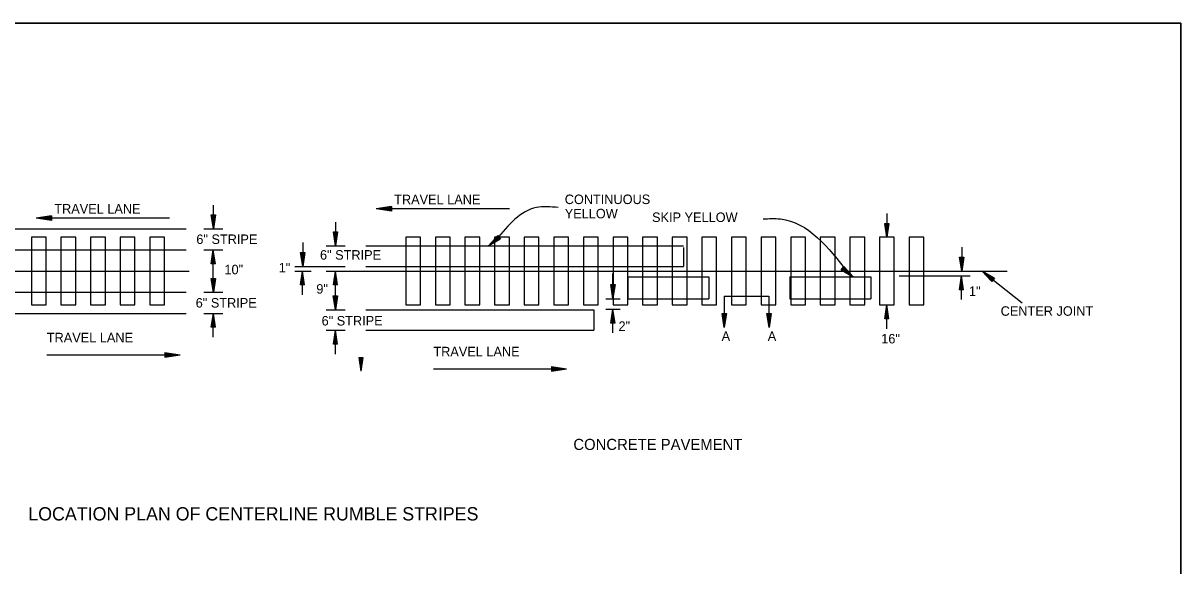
# Model space of a CAD drawing. Extents: x 8229 to 8749, y 14916 to 18021.
# Drawn here: x 8423.6 to 8749, y 16313.4 to 16466 of the extents above; entities that cross this region are included whole.
import ezdxf

# ---------------------------------------------------------------- set-up
doc = ezdxf.new("R2010")
doc.units = 0
doc.layers.add('Default', color=7, linetype='Continuous')
doc.layers.add('R_Draft', color=7, linetype='Continuous')

msp = doc.modelspace()

# ---------------------------------------------------------------- linework, layer by layer
at = {"layer": 'Default'}
for p, q in [((8477.01, 16414.9), (8477.01, 16412.12)), ((8431.51, 16411.84), (8427.26, 16411.2)), ((8431.51, 16411.74), (8427.97, 16411.2)), ((8431.51, 16411.63), (8428.7, 16411.2)), ((8431.51, 16411.52), (8429.41, 16411.2)), ((8431.51, 16411.41), (8430.13, 16411.2)), ((8431.51, 16411.84), (8431.51, 16410.57)), ((8476.45, 16412.12), (8477.03, 16408.21)), ((8476.45, 16412.12), (8477.62, 16412.12)), ((8476.54, 16412.12), (8477.03, 16408.86)), ((8476.64, 16412.12), (8477.03, 16409.53)), ((8476.74, 16412.12), (8477.03, 16410.19)), ((8476.84, 16412.12), (8477.03, 16410.85)), ((8476.94, 16412.12), (8477.03, 16411.5)), ((8477.62, 16412.12), (8477.03, 16408.21)), ((8477.22, 16412.12), (8477.03, 16410.85)), ((8477.42, 16412.12), (8477.03, 16409.53)), ((8477.52, 16412.12), (8477.03, 16408.86)), ((8477.32, 16412.12), (8477.03, 16410.19)), ((8477.12, 16412.12), (8477.03, 16411.5)), ((8527.06, 16414.47), (8522.8, 16413.83)), ((8560.23, 16413.83), (8522.8, 16413.83)), ((8527.06, 16413.19), (8522.8, 16413.83)), ((8527.06, 16414.36), (8523.51, 16413.83)), ((8527.06, 16413.3), (8523.51, 16413.83)), ((8527.06, 16414.26), (8524.24, 16413.83)), ((8527.06, 16413.41), (8524.24, 16413.83)), ((8527.06, 16414.15), (8524.95, 16413.83)), ((8527.06, 16413.52), (8524.95, 16413.83)), ((8527.06, 16414.04), (8525.67, 16413.83)), ((8527.06, 16413.62), (8525.67, 16413.83)), ((8527.06, 16413.93), (8526.38, 16413.83)), ((8527.06, 16413.73), (8526.38, 16413.83)), ((8527.06, 16414.47), (8527.06, 16413.19)), ((8666.34, 16412.52), (8666.34, 16409.73)), ((8464.69, 16411.2), (8427.26, 16411.2)), ((8431.51, 16410.57), (8427.26, 16411.2)), ((8431.51, 16410.67), (8427.97, 16411.2)), ((8431.51, 16410.78), (8428.7, 16411.2)), ((8431.51, 16410.89), (8429.41, 16411.2)), ((8431.51, 16410.99), (8430.13, 16411.2)), ((8431.51, 16411.3), (8430.84, 16411.2)), ((8431.51, 16411.1), (8430.84, 16411.2)), ((8474.36, 16408.21), (8479.7, 16408.21)), ((8511.34, 16410.13), (8511.34, 16407.35)), ((8665.77, 16409.73), (8666.36, 16405.83)), ((8665.77, 16409.73), (8666.94, 16409.73)), ((8665.87, 16409.73), (8666.36, 16406.48)), ((8665.97, 16409.73), (8666.36, 16407.15)), ((8666.07, 16409.73), (8666.36, 16407.8)), ((8666.17, 16409.73), (8666.36, 16408.46)), ((8666.26, 16409.73), (8666.36, 16409.12)), ((8666.94, 16409.73), (8666.36, 16405.83)), ((8666.55, 16409.73), (8666.36, 16408.46)), ((8666.74, 16409.73), (8666.36, 16407.15)), ((8666.84, 16409.73), (8666.36, 16406.48)), ((8666.65, 16409.73), (8666.36, 16407.8)), ((8666.45, 16409.73), (8666.36, 16409.12)), ((8510.77, 16407.35), (8511.36, 16403.45)), ((8510.77, 16407.35), (8511.94, 16407.35)), ((8510.87, 16407.35), (8511.36, 16404.1)), ((8510.97, 16407.35), (8511.36, 16404.77)), ((8511.07, 16407.35), (8511.36, 16405.42)), ((8511.17, 16407.35), (8511.36, 16406.08)), ((8511.27, 16407.35), (8511.36, 16406.73)), ((8511.94, 16407.35), (8511.36, 16403.45)), ((8511.55, 16407.35), (8511.36, 16406.08)), ((8511.75, 16407.35), (8511.36, 16404.77)), ((8511.84, 16407.35), (8511.36, 16404.1)), ((8511.65, 16407.35), (8511.36, 16405.42)), ((8511.45, 16407.35), (8511.36, 16406.73)), ((8557.02, 16406.35), (8554.34, 16403.45)), ((8557.75, 16405.43), (8554.34, 16403.45)), ((8557.08, 16406.27), (8554.85, 16403.85)), ((8557.69, 16405.51), (8554.85, 16403.85)), ((8557.14, 16406.19), (8555.38, 16404.27)), ((8557.63, 16405.59), (8555.38, 16404.27)), ((8557.21, 16406.12), (8555.88, 16404.68)), ((8557.57, 16405.66), (8555.88, 16404.68)), ((8557.27, 16406.04), (8556.4, 16405.09)), ((8557.51, 16405.74), (8556.4, 16405.09)), ((8557.33, 16405.96), (8556.91, 16405.5)), ((8557.45, 16405.82), (8556.91, 16405.5)), ((8557.02, 16406.35), (8557.75, 16405.43)), ((8474.36, 16402.27), (8479.7, 16402.27)), ((8476.43, 16398.36), (8477.01, 16402.27)), ((8476.53, 16398.36), (8477.01, 16401.61)), ((8477.01, 16390.38), (8477.01, 16402.27)), ((8477.6, 16398.36), (8477.01, 16402.27)), ((8477.5, 16398.36), (8477.01, 16401.61)), ((8502.13, 16404.34), (8502.13, 16401.56)), ((8508.69, 16403.45), (8514.03, 16403.45)), ((8687.38, 16403.01), (8687.38, 16400.22)), ((8477.6, 16398.36), (8476.43, 16398.36)), ((8476.63, 16398.36), (8477.01, 16400.94)), ((8476.72, 16398.36), (8477.01, 16400.29)), ((8476.82, 16398.36), (8477.01, 16399.63)), ((8476.92, 16398.36), (8477.01, 16398.98)), ((8477.4, 16398.36), (8477.01, 16400.94)), ((8477.31, 16398.36), (8477.01, 16400.29)), ((8477.2, 16398.36), (8477.01, 16399.63)), ((8477.11, 16398.36), (8477.01, 16398.98)), ((8501.56, 16401.56), (8502.15, 16397.66)), ((8501.56, 16401.56), (8502.73, 16401.56)), ((8501.66, 16401.56), (8502.15, 16398.31)), ((8501.76, 16401.56), (8502.15, 16398.98)), ((8501.86, 16401.56), (8502.15, 16399.63)), ((8501.96, 16401.56), (8502.15, 16400.29)), ((8502.06, 16401.56), (8502.15, 16400.94)), ((8502.73, 16401.56), (8502.15, 16397.66)), ((8502.34, 16401.56), (8502.15, 16400.29)), ((8502.54, 16401.56), (8502.15, 16398.98)), ((8502.64, 16401.56), (8502.15, 16398.31)), ((8502.44, 16401.56), (8502.15, 16399.63)), ((8502.24, 16401.56), (8502.15, 16400.94)), ((8686.81, 16400.22), (8687.4, 16396.32)), ((8686.81, 16400.22), (8687.98, 16400.22)), ((8686.91, 16400.22), (8687.4, 16396.97)), ((8687.01, 16400.22), (8687.4, 16397.64)), ((8687.11, 16400.22), (8687.4, 16398.29)), ((8687.21, 16400.22), (8687.4, 16398.96)), ((8687.31, 16400.22), (8687.4, 16399.61)), ((8687.98, 16400.22), (8687.4, 16396.32)), ((8687.59, 16400.22), (8687.4, 16398.96)), ((8687.79, 16400.22), (8687.4, 16397.64)), ((8687.89, 16400.22), (8687.4, 16396.97)), ((8687.69, 16400.22), (8687.4, 16398.29)), ((8687.49, 16400.22), (8687.4, 16399.61)), ((8305.76, 16396.32), (8470.2, 16396.32)), ((8499.9, 16397.66), (8514.03, 16397.66)), ((8499.9, 16396.32), (8504.52, 16396.32)), ((8501.51, 16392.42), (8502.1, 16396.32)), ((8501.61, 16392.42), (8502.1, 16395.67)), ((8502.68, 16392.42), (8502.1, 16396.32)), ((8502.59, 16392.42), (8502.1, 16395.67)), ((8508.69, 16396.32), (8700.13, 16396.32)), ((8510.75, 16392.42), (8511.34, 16396.32)), ((8510.85, 16392.42), (8511.34, 16395.67)), ((8511.34, 16385.46), (8511.34, 16396.32)), ((8511.92, 16392.42), (8511.34, 16396.32)), ((8511.83, 16392.42), (8511.34, 16395.67)), ((8589.33, 16388.61), (8589.33, 16395.64)), ((8653.48, 16396.72), (8654.21, 16397.64)), ((8653.48, 16396.72), (8656.9, 16394.75)), ((8653.54, 16396.8), (8656.39, 16395.15)), ((8653.6, 16396.88), (8655.86, 16395.57)), ((8653.67, 16396.95), (8655.36, 16395.98)), ((8653.73, 16397.03), (8654.84, 16396.39)), ((8653.79, 16397.11), (8654.33, 16396.8)), ((8653.9, 16397.25), (8654.33, 16396.8)), ((8653.97, 16397.33), (8654.84, 16396.39)), ((8654.03, 16397.41), (8655.36, 16395.98)), ((8654.09, 16397.48), (8655.86, 16395.57)), ((8654.15, 16397.56), (8656.39, 16395.15)), ((8654.21, 16397.64), (8656.9, 16394.75)), ((8693.16, 16396.32), (8704.34, 16387.41)), ((8696.57, 16394.35), (8693.16, 16396.32)), ((8695.84, 16393.43), (8693.16, 16396.32)), ((8696.51, 16394.27), (8693.67, 16395.91)), ((8695.9, 16393.51), (8693.67, 16395.91)), ((8695.97, 16393.58), (8694.19, 16395.5)), ((8696.45, 16394.19), (8694.19, 16395.5)), ((8696.39, 16394.11), (8694.7, 16395.09)), ((8696.03, 16393.66), (8694.7, 16395.09)), ((8476.45, 16394.28), (8477.03, 16390.38)), ((8476.45, 16394.28), (8477.62, 16394.28)), ((8476.54, 16394.28), (8477.03, 16391.03)), ((8476.64, 16394.28), (8477.03, 16391.7)), ((8476.74, 16394.28), (8477.03, 16392.35)), ((8476.84, 16394.28), (8477.03, 16393.01)), ((8476.94, 16394.28), (8477.03, 16393.66)), ((8477.62, 16394.28), (8477.03, 16390.38)), ((8477.22, 16394.28), (8477.03, 16393.01)), ((8477.42, 16394.28), (8477.03, 16391.7)), ((8477.52, 16394.28), (8477.03, 16391.03)), ((8477.32, 16394.28), (8477.03, 16392.35)), ((8477.12, 16394.28), (8477.03, 16393.66)), ((8502.68, 16392.42), (8501.51, 16392.42)), ((8501.71, 16392.42), (8502.1, 16395)), ((8501.81, 16392.42), (8502.1, 16394.35)), ((8501.91, 16392.42), (8502.1, 16393.69)), ((8502.01, 16392.42), (8502.1, 16393.03)), ((8502.08, 16389.63), (8502.08, 16392.42)), ((8502.49, 16392.42), (8502.1, 16395)), ((8502.39, 16392.42), (8502.1, 16394.35)), ((8502.29, 16392.42), (8502.1, 16393.69)), ((8502.19, 16392.42), (8502.1, 16393.03)), ((8511.92, 16392.42), (8510.75, 16392.42)), ((8510.95, 16392.42), (8511.34, 16395)), ((8511.05, 16392.42), (8511.34, 16394.35)), ((8511.15, 16392.42), (8511.34, 16393.69)), ((8511.25, 16392.42), (8511.34, 16393.03)), ((8511.73, 16392.42), (8511.34, 16395)), ((8511.63, 16392.42), (8511.34, 16394.35)), ((8511.53, 16392.42), (8511.34, 16393.69)), ((8511.43, 16392.42), (8511.34, 16393.03)), ((8588.77, 16392.51), (8589.35, 16388.61)), ((8588.77, 16392.51), (8589.94, 16392.51)), ((8588.86, 16392.51), (8589.35, 16389.26)), ((8588.96, 16392.51), (8589.35, 16389.93)), ((8589.06, 16392.51), (8589.35, 16390.58)), ((8589.16, 16392.51), (8589.35, 16391.24)), ((8589.26, 16392.51), (8589.35, 16391.89)), ((8589.94, 16392.51), (8589.35, 16388.61)), ((8589.54, 16392.51), (8589.35, 16391.24)), ((8589.74, 16392.51), (8589.35, 16389.93)), ((8589.84, 16392.51), (8589.35, 16389.26)), ((8589.64, 16392.51), (8589.35, 16390.58)), ((8589.44, 16392.51), (8589.35, 16391.89)), ((8669.79, 16394.99), (8689.77, 16394.99)), ((8686.76, 16391.08), (8687.35, 16394.99)), ((8686.86, 16391.08), (8687.35, 16394.33)), ((8686.96, 16391.08), (8687.35, 16393.66)), ((8687.06, 16391.08), (8687.35, 16393.01)), ((8687.16, 16391.08), (8687.35, 16392.35)), ((8687.93, 16391.08), (8687.35, 16394.99)), ((8687.84, 16391.08), (8687.35, 16394.33)), ((8687.74, 16391.08), (8687.35, 16393.66)), ((8687.64, 16391.08), (8687.35, 16393.01)), ((8687.54, 16391.08), (8687.35, 16392.35)), ((8696.09, 16393.74), (8695.22, 16394.68)), ((8696.33, 16394.04), (8695.22, 16394.68)), ((8696.15, 16393.82), (8695.73, 16394.27)), ((8696.26, 16393.96), (8695.73, 16394.27)), ((8696.57, 16394.35), (8695.84, 16393.43)), ((8474.36, 16390.38), (8479.7, 16390.38)), ((8510.75, 16389.36), (8511.34, 16385.46)), ((8510.75, 16389.36), (8511.92, 16389.36)), ((8510.85, 16389.36), (8511.34, 16386.11)), ((8510.95, 16389.36), (8511.34, 16386.78)), ((8511.05, 16389.36), (8511.34, 16387.43)), ((8511.15, 16389.36), (8511.34, 16388.09)), ((8511.25, 16389.36), (8511.34, 16388.74)), ((8511.92, 16389.36), (8511.34, 16385.46)), ((8511.53, 16389.36), (8511.34, 16388.09)), ((8511.73, 16389.36), (8511.34, 16386.78)), ((8511.83, 16389.36), (8511.34, 16386.11)), ((8511.63, 16389.36), (8511.34, 16387.43)), ((8511.43, 16389.36), (8511.34, 16388.74)), ((8620.62, 16389.26), (8620.62, 16384.39)), ((8620.62, 16389.26), (8633.21, 16389.26)), ((8633.21, 16389.26), (8633.21, 16384.39)), ((8687.93, 16391.08), (8686.76, 16391.08)), ((8687.26, 16391.08), (8687.35, 16391.7)), ((8687.33, 16388.3), (8687.33, 16391.08)), ((8687.44, 16391.08), (8687.35, 16391.7)), ((8508.69, 16385.46), (8514.03, 16385.46)), ((8588.77, 16381.73), (8589.35, 16385.63)), ((8589.94, 16381.73), (8589.35, 16385.63)), ((8665.77, 16382.91), (8666.36, 16386.81)), ((8665.87, 16382.91), (8666.36, 16386.16)), ((8665.97, 16382.91), (8666.36, 16385.49)), ((8666.94, 16382.91), (8666.36, 16386.81)), ((8666.84, 16382.91), (8666.36, 16386.16)), ((8666.74, 16382.91), (8666.36, 16385.49)), ((8474.36, 16384.43), (8479.7, 16384.43)), ((8476.45, 16380.53), (8477.03, 16384.43)), ((8476.55, 16380.53), (8477.03, 16383.78)), ((8476.64, 16380.53), (8477.03, 16383.11)), ((8476.74, 16380.53), (8477.03, 16382.46)), ((8477.62, 16380.53), (8477.03, 16384.43)), ((8477.52, 16380.53), (8477.03, 16383.78)), ((8477.42, 16380.53), (8477.03, 16383.11)), ((8477.32, 16380.53), (8477.03, 16382.46)), ((8588.86, 16381.73), (8589.35, 16384.98)), ((8588.96, 16381.73), (8589.35, 16384.31)), ((8589.06, 16381.73), (8589.35, 16383.66)), ((8589.16, 16381.73), (8589.35, 16383)), ((8589.26, 16381.73), (8589.35, 16382.35)), ((8589.84, 16381.73), (8589.35, 16384.98)), ((8589.74, 16381.73), (8589.35, 16384.31)), ((8589.64, 16381.73), (8589.35, 16383.66)), ((8589.54, 16381.73), (8589.35, 16383)), ((8589.44, 16381.73), (8589.35, 16382.35)), ((8620.05, 16384.39), (8620.64, 16380.49)), ((8620.05, 16384.39), (8621.22, 16384.39)), ((8620.15, 16384.39), (8620.64, 16381.14)), ((8620.25, 16384.39), (8620.64, 16381.81)), ((8620.34, 16384.39), (8620.64, 16382.46)), ((8620.45, 16384.39), (8620.64, 16383.12)), ((8620.54, 16384.39), (8620.64, 16383.77)), ((8621.22, 16384.39), (8620.64, 16380.49)), ((8620.83, 16384.39), (8620.64, 16383.12)), ((8621.02, 16384.39), (8620.64, 16381.81)), ((8621.12, 16384.39), (8620.64, 16381.14)), ((8620.93, 16384.39), (8620.64, 16382.46)), ((8620.73, 16384.39), (8620.64, 16383.77)), ((8632.65, 16384.39), (8633.23, 16380.49)), ((8632.65, 16384.39), (8633.82, 16384.39)), ((8632.74, 16384.39), (8633.23, 16381.14)), ((8632.84, 16384.39), (8633.23, 16381.81)), ((8632.94, 16384.39), (8633.23, 16382.46)), ((8633.04, 16384.39), (8633.23, 16383.12)), ((8633.14, 16384.39), (8633.23, 16383.77)), ((8633.82, 16384.39), (8633.23, 16380.49)), ((8633.42, 16384.39), (8633.23, 16383.12)), ((8633.62, 16384.39), (8633.23, 16381.81)), ((8633.72, 16384.39), (8633.23, 16381.14)), ((8633.52, 16384.39), (8633.23, 16382.46)), ((8633.32, 16384.39), (8633.23, 16383.77)), ((8666.94, 16382.91), (8665.77, 16382.91)), ((8666.07, 16382.91), (8666.36, 16384.84)), ((8666.16, 16382.91), (8666.36, 16384.18)), ((8666.26, 16382.91), (8666.36, 16383.53)), ((8666.34, 16380.12), (8666.34, 16382.91)), ((8666.65, 16382.91), (8666.36, 16384.84)), ((8666.55, 16382.91), (8666.36, 16384.18)), ((8666.45, 16382.91), (8666.36, 16383.53)), ((8477.62, 16380.53), (8476.45, 16380.53)), ((8476.84, 16380.53), (8477.03, 16381.8)), ((8476.94, 16380.53), (8477.03, 16381.14)), ((8477.01, 16377.74), (8477.01, 16380.53)), ((8477.22, 16380.53), (8477.03, 16381.8)), ((8477.12, 16380.53), (8477.03, 16381.14)), ((8508.69, 16379.67), (8514.03, 16379.67)), ((8510.77, 16375.76), (8511.36, 16379.67)), ((8510.87, 16375.76), (8511.36, 16379.01)), ((8511.94, 16375.76), (8511.36, 16379.67)), ((8511.85, 16375.76), (8511.36, 16379.01)), ((8589.94, 16381.73), (8588.77, 16381.73)), ((8589.33, 16378.95), (8589.33, 16381.73)), ((8511.94, 16375.76), (8510.77, 16375.76)), ((8510.97, 16375.76), (8511.36, 16378.34)), ((8511.07, 16375.76), (8511.36, 16377.69)), ((8511.17, 16375.76), (8511.36, 16377.03)), ((8511.27, 16375.76), (8511.36, 16376.38)), ((8511.34, 16372.98), (8511.34, 16375.76)), ((8511.75, 16375.76), (8511.36, 16378.34)), ((8511.65, 16375.76), (8511.36, 16377.69)), ((8511.55, 16375.76), (8511.36, 16377.03)), ((8511.45, 16375.76), (8511.36, 16376.38)), ((8430.24, 16372.75), (8467.67, 16372.75)), ((8463.41, 16373.39), (8467.67, 16372.75)), ((8463.41, 16373.39), (8463.41, 16372.12)), ((8463.41, 16373.29), (8466.96, 16372.75)), ((8463.41, 16373.18), (8466.22, 16372.75)), ((8463.41, 16373.07), (8465.51, 16372.75)), ((8463.41, 16372.96), (8464.79, 16372.75)), ((8463.41, 16372.85), (8464.08, 16372.75)), ((8463.41, 16372.12), (8467.67, 16372.75)), ((8463.41, 16372.55), (8464.79, 16372.75)), ((8463.41, 16372.33), (8466.22, 16372.75)), ((8463.41, 16372.22), (8466.96, 16372.75)), ((8463.41, 16372.44), (8465.51, 16372.75)), ((8463.41, 16372.65), (8464.08, 16372.75)), ((8517.9, 16372.05), (8518.49, 16368.15)), ((8517.9, 16372.05), (8519.07, 16372.05)), ((8518, 16372.05), (8518.49, 16368.8)), ((8518.1, 16372.05), (8518.49, 16369.47)), ((8518.2, 16372.05), (8518.49, 16370.12)), ((8518.3, 16372.05), (8518.49, 16370.78)), ((8518.39, 16372.05), (8518.49, 16371.43)), ((8519.07, 16372.05), (8518.49, 16368.15)), ((8518.68, 16372.05), (8518.49, 16370.78)), ((8518.87, 16372.05), (8518.49, 16369.47)), ((8518.97, 16372.05), (8518.49, 16368.8)), ((8518.78, 16372.05), (8518.49, 16370.12)), ((8518.58, 16372.05), (8518.49, 16371.43)), ((8572.07, 16369.46), (8576.33, 16368.82)), ((8572.07, 16369.46), (8572.07, 16368.18)), ((8572.07, 16369.35), (8575.62, 16368.82)), ((8572.07, 16369.24), (8574.89, 16368.82)), ((8572.07, 16369.14), (8574.18, 16368.82)), ((8538.9, 16368.82), (8576.33, 16368.82)), ((8572.07, 16369.03), (8573.46, 16368.82)), ((8572.07, 16368.92), (8572.75, 16368.82)), ((8572.07, 16368.18), (8576.33, 16368.82)), ((8572.07, 16368.61), (8573.46, 16368.82)), ((8572.07, 16368.4), (8574.89, 16368.82)), ((8572.07, 16368.29), (8575.62, 16368.82)), ((8572.07, 16368.5), (8574.18, 16368.82)), ((8572.07, 16368.72), (8572.75, 16368.82))]:
    msp.add_line(p, q, dxfattribs=at)
for points in [[(8230.82, 16466.05), (8748.98, 16466.05), (8748.98, 16130.77), (8230.82, 16130.77)], [(8230.82, 16466.05), (8230.82, 16130.77), (8748.98, 16130.77), (8748.98, 16466.05)], [(8425.86, 16405.83), (8425.86, 16386.81), (8430.02, 16386.81), (8430.02, 16405.83)], [(8434.19, 16405.83), (8434.19, 16386.81), (8438.35, 16386.81), (8438.35, 16405.83)], [(8442.51, 16405.83), (8442.51, 16386.81), (8446.67, 16386.81), (8446.67, 16405.83)], [(8450.83, 16405.83), (8450.83, 16386.81), (8454.99, 16386.81), (8454.99, 16405.83)], [(8459.16, 16405.83), (8459.16, 16386.81), (8463.32, 16386.81), (8463.32, 16405.83)], [(8531.1, 16405.83), (8531.1, 16386.81), (8535.26, 16386.81), (8535.26, 16405.83)], [(8539.43, 16405.83), (8539.43, 16386.81), (8543.59, 16386.81), (8543.59, 16405.83)], [(8547.75, 16405.83), (8547.75, 16386.81), (8551.91, 16386.81), (8551.91, 16405.83)], [(8556.07, 16405.83), (8556.07, 16386.81), (8560.23, 16386.81), (8560.23, 16405.83)], [(8564.4, 16405.83), (8564.4, 16386.81), (8568.56, 16386.81), (8568.56, 16405.83)], [(8572.72, 16405.83), (8572.72, 16386.81), (8576.88, 16386.81), (8576.88, 16405.83)], [(8581.04, 16405.83), (8581.04, 16386.81), (8585.2, 16386.81), (8585.2, 16405.83)], [(8589.37, 16405.83), (8589.37, 16386.81), (8593.53, 16386.81), (8593.53, 16405.83)], [(8597.69, 16405.83), (8597.69, 16386.81), (8601.85, 16386.81), (8601.85, 16405.83)], [(8606.01, 16405.83), (8606.01, 16386.81), (8610.17, 16386.81), (8610.17, 16405.83)], [(8614.34, 16405.83), (8614.34, 16386.81), (8618.5, 16386.81), (8618.5, 16405.83)], [(8622.66, 16405.83), (8622.66, 16386.81), (8626.82, 16386.81), (8626.82, 16405.83)], [(8630.98, 16405.83), (8630.98, 16386.81), (8635.14, 16386.81), (8635.14, 16405.83)], [(8639.31, 16405.83), (8639.31, 16386.81), (8643.47, 16386.81), (8643.47, 16405.83)], [(8647.63, 16405.83), (8647.63, 16386.81), (8651.79, 16386.81), (8651.79, 16405.83)], [(8655.95, 16405.83), (8655.95, 16386.81), (8660.11, 16386.81), (8660.11, 16405.83)], [(8664.28, 16405.83), (8664.28, 16386.81), (8668.44, 16386.81), (8668.44, 16405.83)], [(8672.6, 16405.83), (8672.6, 16386.81), (8676.76, 16386.81), (8676.76, 16405.83)]]:
    msp.add_lwpolyline(points, close=True, dxfattribs=at)
for points in [[(8573.95, 16414.19), (8567.82, 16414.19), (8556.56, 16405.23)], [(8631.53, 16411), (8636.43, 16411), (8655.41, 16395.88)]]:
    msp.add_spline(points, degree=3, dxfattribs=at)
at = {"layer": 'R_Draft'}
for p, q in [((8392.61, 16408.21), (8469.41, 16408.21)), ((8392.61, 16402.27), (8469.41, 16402.27)), ((8519.92, 16403.45), (8609.17, 16403.45)), ((8609.17, 16403), (8609.17, 16397.66)), ((8519.92, 16397.66), (8609.17, 16397.66)), ((8593.57, 16394.75), (8593.57, 16388.53)), ((8593.57, 16394.75), (8616.3, 16394.75)), ((8616.3, 16394.75), (8616.3, 16388.53)), ((8639.08, 16394.75), (8639.08, 16388.53)), ((8639.08, 16394.75), (8661.81, 16394.75)), ((8661.81, 16394.75), (8661.81, 16388.53)), ((8348.81, 16390.38), (8469.41, 16390.38)), ((8519.92, 16385.46), (8583.93, 16385.46)), ((8583.93, 16385.46), (8583.93, 16379.67)), ((8587.31, 16388.53), (8591.39, 16388.53)), ((8587.31, 16385.63), (8591.39, 16385.63)), ((8593.57, 16388.53), (8616.3, 16388.53)), ((8639.08, 16388.53), (8661.81, 16388.53)), ((8348.81, 16384.43), (8469.41, 16384.43)), ((8519.92, 16379.67), (8583.93, 16379.67))]:
    msp.add_line(p, q, dxfattribs=at)
for points in [[(8476.43, 16412.12), (8477.6, 16412.12), (8477.03, 16408.21)], [(8665.75, 16409.73), (8666.93, 16409.73), (8666.36, 16405.83)], [(8510.75, 16407.35), (8511.93, 16407.35), (8511.36, 16403.45)], [(8557.46, 16405.25), (8556.8, 16406.09), (8554.34, 16403.45)], [(8501.54, 16401.56), (8502.72, 16401.56), (8502.15, 16397.66)], [(8686.79, 16400.22), (8687.97, 16400.22), (8687.4, 16396.32)], [(8653.78, 16396.56), (8654.45, 16397.39), (8656.9, 16394.75)], [(8696.27, 16394.51), (8695.61, 16393.67), (8693.16, 16396.32)], [(8476.43, 16394.28), (8477.6, 16394.28), (8477.03, 16390.38)], [(8588.75, 16392.51), (8589.92, 16392.51), (8589.35, 16388.61)], [(8510.73, 16389.36), (8511.91, 16389.36), (8511.34, 16385.46)], [(8620.03, 16384.39), (8621.21, 16384.39), (8620.64, 16380.49)], [(8632.63, 16384.39), (8633.8, 16384.39), (8633.23, 16380.49)]]:
    msp.add_lwpolyline(points, close=True, dxfattribs=at)

# ---------------------------------------------------------------- texts
at = {"layer": 'Default'}
for s, height, p in [('CONTINUOUS ', 2.6734, (8575.8, 16415.17)), ('TRAVEL LANE', 2.6734, (8432.31, 16412.5)), ('TRAVEL LANE', 2.6734, (8527.85, 16415.13)), ('YELLOW', 2.673, (8575.8, 16411.16)), ('SKIP YELLOW', 2.6734, (8600.34, 16410.13)), ('6" STRIPE', 2.673, (8472.24, 16403.95)), ('6" STRIPE', 2.673, (8507.01, 16399.54)), ('1"', 2.673, (8495.4, 16395.96)), ('10"', 2.673, (8480.14, 16395.44)), ('9"', 2.673, (8505.97, 16389.98)), ('1"', 2.673, (8689.42, 16389.35)), ('6" STRIPE', 2.673, (8472.06, 16386.07)), ('CENTER JOINT', 2.6734, (8698.34, 16383.76)), ('6" STRIPE', 2.673, (8507.45, 16381.03)), ('2"', 2.673, (8590.91, 16379.51)), ('TRAVEL LANE', 2.6734, (8430.21, 16376.3)), ('A', 2.67, (8619.9, 16376.7)), ('A', 2.67, (8632.86, 16376.7)), ('16"', 2.673, (8664.77, 16375.98)), ('TRAVEL LANE', 2.6734, (8538.87, 16372.36)), ('CONCRETE PAVEMENT', 3.119, (8578.22, 16346.03))]:
    msp.add_text(s, height=height, dxfattribs=at).set_placement(p)
at = {"layer": 'R_Draft'}
msp.add_text('LOCATION PLAN OF CENTERLINE RUMBLE STRIPES', height=3.7428, dxfattribs=at).set_placement((8425, 16326.2))

doc.saveas('drawing.dxf')
